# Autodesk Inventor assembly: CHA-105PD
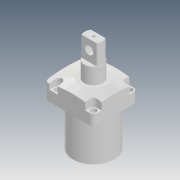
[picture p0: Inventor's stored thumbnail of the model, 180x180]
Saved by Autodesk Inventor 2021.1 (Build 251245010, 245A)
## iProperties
Created: 2018-11
Part Number: CHA-105PD
Description: STEP AP214
Document SubType Name: Assembly
Designer: user
Title: CHA-105PD.STEP
Revision Number: ÈÎºÎ
Sending System: SolidWorks 2016
Preprocessor: SwSTEP 2.0
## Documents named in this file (4)
- D:\Vault_2016\Projekty\Clamptek\Hydraulic\CHA-P\Inventor\CHA-105PD\CHA-105PD.iam
- D:\Vault_2016\Projekty\Clamptek\Hydraulic\CHA-P\Inventor\CHA-105PD\CHA-105PSR-90(BT).ipt
- D:\Vault_2016\Projekty\Clamptek\Hydraulic\CHA-P\Inventor\CHA-105PD\CHA-105PD(HSG).ipt
- D:\Vault_2016\Projekty\Clamptek\Hydraulic\CHA-P\Inventor\CHA-105PD\G3-8¶ÂÍ·.ipt
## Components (4 placed, 4 different names)
1. CHA-105PSR-90(BT)_1
2. CHA-105PD(HSG)_2
3. G3-8¶ÂÍ·_3
4. G3-8¶ÂÍ·_4
